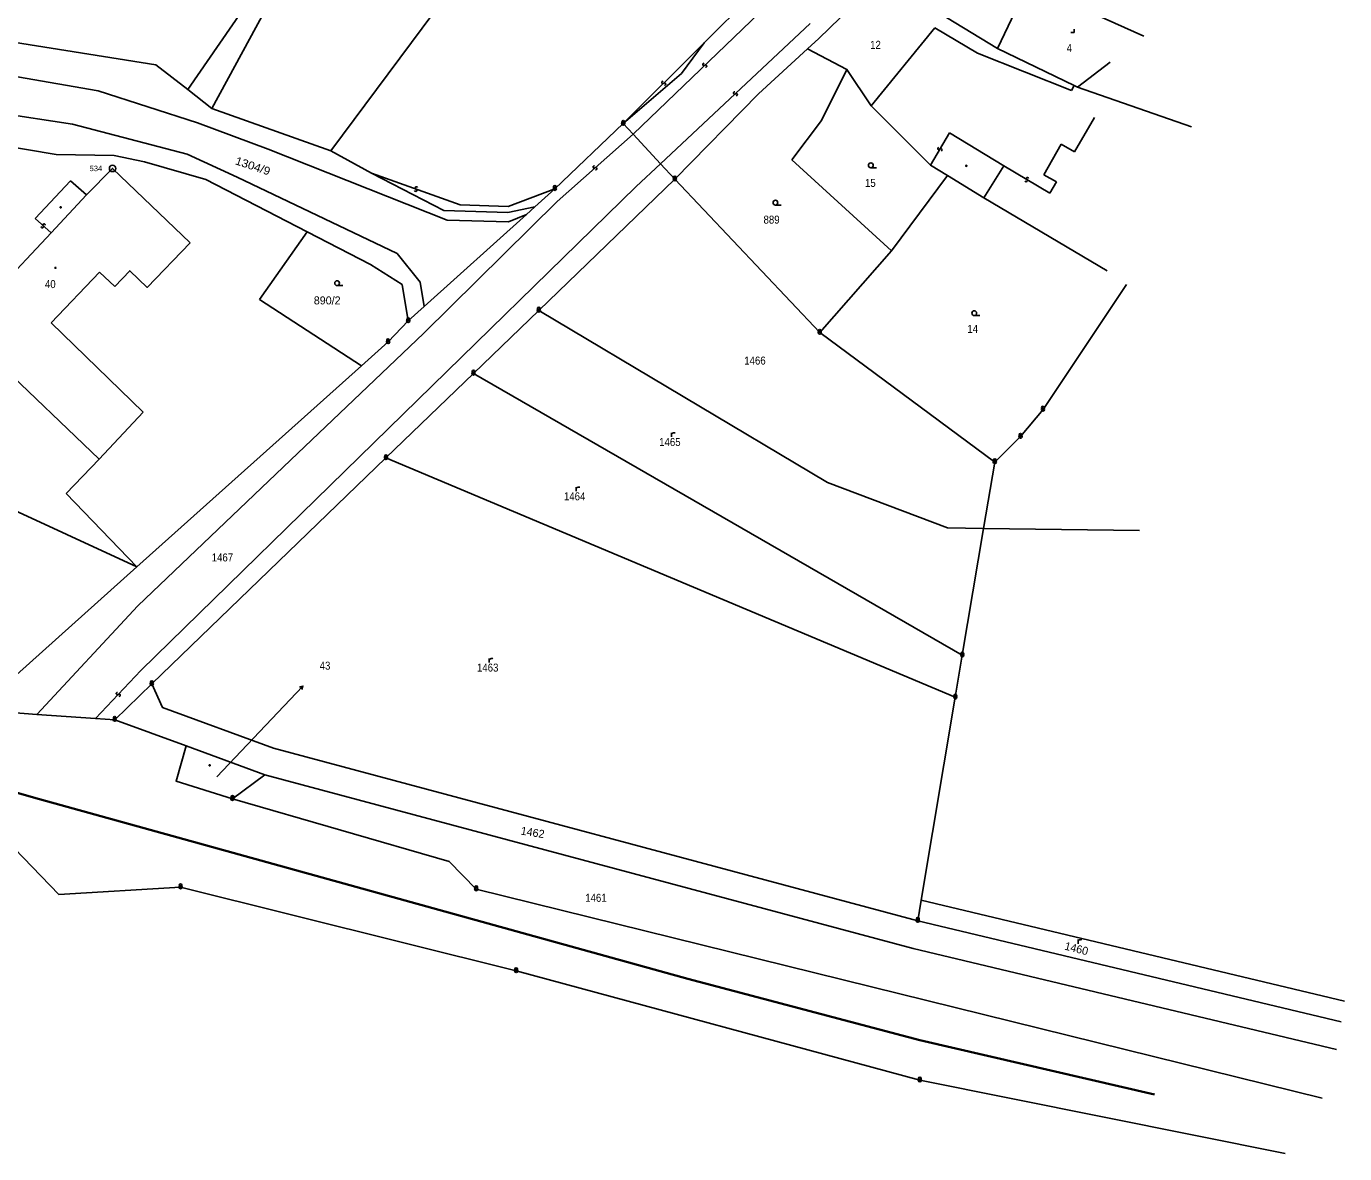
# Model space of a CAD drawing. Extents: x -871901 to -870967, y -1075952 to -1074892.
# Drawn here: x -871194.5 to -871029.7, y -1075430.9 to -1075290 of the extents above; entities that cross this region are included whole.
import ezdxf
from ezdxf.enums import TextEntityAlignment as Align

# ---------------------------------------------------------------- set-up
doc = ezdxf.new("R2010")
doc.units = 0
doc.header["$LTSCALE"] = 0.4
for name, color, linetype, lineweight in [('1', 7, 'Continuous', 25), ('10', 7, 'Continuous', 35), ('16', 7, 'Continuous', 25), ('24', 7, 'Continuous', 25), ('25', 7, 'Continuous', 25), ('4', 7, 'Continuous', 25)]:
    doc.layers.add(name, color=color, linetype=linetype, lineweight=lineweight)
for name, color, linetype in [('17', 7, 'Continuous'), ('18', 7, 'Continuous'), ('19', 7, 'Continuous')]:
    doc.layers.add(name, color=color, linetype=linetype)

msp = doc.modelspace()

# ---------------------------------------------------------------- linework, layer by layer
at = {"layer": '1'}
for p, q in [((-871156.43, -1075305.59), (-871115.7, -1075250.9)), ((-871174.28, -1075297.93), (-871154.05, -1075268.6)), ((-871109.75, -1075292.07), (-871095.22, -1075277.55)), ((-871095.43, -1075291.53), (-871087.07, -1075283.41)), ((-871073.1, -1075292.79), (-871069.29, -1075284.78)), ((-871084.21, -1075286.02), (-871073.1, -1075292.79)), ((-871064.49, -1075286.92), (-871054.81, -1075291.23)), ((-871088.88, -1075299.94), (-871080.94, -1075290.22)), ((-871080.94, -1075290.22), (-871075.62, -1075293.36)), ((-871197.94, -1075291.72), (-871178.28, -1075294.81)), ((-871112.61, -1075295.91), (-871109.75, -1075292.07)), ((-871096.84, -1075292.82), (-871095.43, -1075291.53)), ((-871102.97, -1075298.45), (-871096.84, -1075292.82)), ((-871096.84, -1075292.82), (-871091.92, -1075295.42)), ((-871075.62, -1075293.36), (-871063.87, -1075298.04)), ((-871073.1, -1075292.79), (-871063.52, -1075297.41)), ((-871178.28, -1075294.81), (-871174.28, -1075297.93)), ((-871119.87, -1075302.18), (-871112.61, -1075295.91)), ((-871063.87, -1075298.04), (-871063.52, -1075297.41)), ((-871174.28, -1075297.93), (-871171.28, -1075300.27)), ((-871113.42, -1075309.13), (-871102.97, -1075298.45)), ((-871063.11, -1075297.61), (-871048.84, -1075302.56)), ((-871171.28, -1075300.27), (-871156.43, -1075305.59)), ((-871088.88, -1075299.94), (-871081.48, -1075307.38)), ((-871128.42, -1075310.32), (-871119.87, -1075302.18)), ((-871119.87, -1075302.18), (-871118.65, -1075303.5)), ((-871098.8, -1075306.71), (-871095.1, -1075301.79)), ((-871118.65, -1075303.5), (-871115.21, -1075307.2)), ((-871198.89, -1075304.69), (-871190.75, -1075306.03)), ((-871156.43, -1075305.59), (-871151.31, -1075308.38)), ((-871190.75, -1075306.03), (-871183.47, -1075306.17)), ((-871183.47, -1075306.17), (-871179.69, -1075306.97)), ((-871179.69, -1075306.97), (-871172.04, -1075309.18)), ((-871115.21, -1075307.2), (-871113.42, -1075309.13)), ((-871098.8, -1075306.71), (-871086.34, -1075318.08)), ((-871151.31, -1075308.38), (-871142.29, -1075313.05)), ((-871086.34, -1075318.08), (-871079.33, -1075308.68)), ((-871172.04, -1075309.18), (-871159.38, -1075315.72)), ((-871113.42, -1075309.13), (-871095.32, -1075328.3)), ((-871074.79, -1075311.44), (-871059.4, -1075320.6)), ((-871142.29, -1075313.05), (-871134.29, -1075313.31)), ((-871134.29, -1075313.31), (-871130.92, -1075312.57)), ((-871165.34, -1075324.15), (-871159.38, -1075315.72)), ((-871159.38, -1075315.72), (-871151.47, -1075319.8)), ((-871095.32, -1075328.3), (-871086.34, -1075318.08)), ((-871151.47, -1075319.8), (-871147.48, -1075322.31)), ((-871147.48, -1075322.31), (-871146.74, -1075326.85)), ((-871067.41, -1075337.92), (-871056.96, -1075322.27)), ((-871165.34, -1075324.15), (-871152.59, -1075332.45)), ((-871149.26, -1075329.47), (-871146.74, -1075326.85)), ((-871130.43, -1075325.54), (-871094.35, -1075347.04)), ((-871202.55, -1075327.7), (-871185.37, -1075344.12)), ((-871095.32, -1075328.3), (-871073.44, -1075344.48)), ((-871152.59, -1075332.45), (-871149.26, -1075329.47)), ((-871180.67, -1075357.59), (-871152.59, -1075332.45)), ((-871138.58, -1075333.41), (-871077.5, -1075368.64)), ((-871070.22, -1075341.31), (-871067.41, -1075337.92)), ((-871218.91, -1075339.87), (-871180.67, -1075357.59)), ((-871073.44, -1075344.48), (-871070.22, -1075341.31)), ((-871189.49, -1075348.43), (-871185.37, -1075344.12)), ((-871078.37, -1075373.89), (-871149.52, -1075343.97)), ((-871189.49, -1075348.43), (-871180.67, -1075357.59))]:
    msp.add_line(p, q, dxfattribs=at)
for points in [[(-871095.1, -1075301.79), (-871091.92, -1075295.42), (-871088.88, -1075299.94)], [(-871063.52, -1075297.41), (-871063.11, -1075297.61), (-871059.04, -1075294.48)], [(-871081.48, -1075307.38), (-871079.33, -1075308.68), (-871074.79, -1075311.44)], [(-871183.42, -1075376.69), (-871178.79, -1075372.22), (-871149.52, -1075343.97), (-871138.58, -1075333.41), (-871130.43, -1075325.54), (-871113.42, -1075309.13)], [(-871131.97, -1075313.52), (-871130.92, -1075312.57), (-871128.42, -1075310.32)], [(-871146.74, -1075326.85), (-871144.74, -1075325.04), (-871131.97, -1075313.52)], [(-871073.44, -1075344.48), (-871074.84, -1075352.78), (-871055.34, -1075353.05)], [(-871094.35, -1075347.04), (-871079.33, -1075352.72), (-871074.84, -1075352.78)], [(-871029.72, -1075411.9), (-871082.62, -1075399.25), (-871078.37, -1075373.89), (-871077.5, -1075368.64), (-871074.84, -1075352.78)], [(-871201.2, -1075375.48), (-871200.62, -1075375.46), (-871180.67, -1075357.59)], [(-871178.79, -1075372.22), (-871177.43, -1075375.17), (-871163.59, -1075380.25), (-871083.05, -1075401.82)], [(-871200.62, -1075375.46), (-871193.17, -1075376.03), (-871185.81, -1075376.53), (-871183.42, -1075376.69)], [(-871183.42, -1075376.69), (-871174.48, -1075379.98), (-871175.76, -1075384.38), (-871168.71, -1075386.58), (-871141.62, -1075394.43), (-871138.24, -1075397.87), (-871032.51, -1075424.01)], [(-871174.48, -1075379.98), (-871164.66, -1075383.59), (-871168.71, -1075386.58)], [(-871164.66, -1075383.59), (-871083.63, -1075405.29), (-871030.73, -1075417.93)], [(-871212.24, -1075392.84), (-871205.94, -1075388.38), (-871204.62, -1075388.86), (-871199.28, -1075390.81), (-871197.08, -1075391.62), (-871190.41, -1075398.53), (-871175.19, -1075397.63)], [(-871037.17, -1075430.94), (-871082.81, -1075421.77), (-871133.25, -1075408.1), (-871175.19, -1075397.63)], [(-871082.62, -1075399.25), (-871083.05, -1075401.82), (-871030.15, -1075414.48)]]:
    msp.add_lwpolyline(points, dxfattribs=at)
at = {"layer": '10'}
msp.add_lwpolyline([(-871303.26, -1075354.3), (-871283.38, -1075360.82), (-871232.19, -1075375.42), (-871192.83, -1075386.61), (-871111.78, -1075409.09), (-871082.8, -1075416.75), (-871053.48, -1075423.53)], dxfattribs=at)
at = {"layer": '16'}
for p, q in [((-871160.73, -1075373.36), (-871159.903, -1075372.489)), ((-871170.66, -1075383.82), (-871160.73, -1075373.36))]:
    msp.add_line(p, q, dxfattribs=at)
msp.add_lwpolyline([(-871160.324, -1075372.642), (-871159.903, -1075372.489), (-871160.034, -1075372.917)], dxfattribs=at)
at = {"layer": '24'}
for centre, radius in [((-871119.8695, -1075302.1795), 0.2005), ((-871119.8695, -1075302.1795), 0.00851), ((-871183.6895, -1075307.7795), 0.4005), ((-871183.6895, -1075307.7795), 0.0125), ((-871113.4195, -1075309.1295), 0.2005), ((-871128.4195, -1075310.3195), 0.2005), ((-871128.4195, -1075310.3195), 0.00851), ((-871113.4195, -1075309.1295), 0.00851), ((-871130.4295, -1075325.5395), 0.2005), ((-871146.7395, -1075326.8495), 0.2005), ((-871146.7395, -1075326.8495), 0.00851), ((-871130.4295, -1075325.5395), 0.00851), ((-871095.3195, -1075328.2995), 0.2005), ((-871095.3195, -1075328.2995), 0.00851), ((-871149.2595, -1075329.4695), 0.2005), ((-871149.2595, -1075329.4695), 0.00851), ((-871138.5795, -1075333.4095), 0.2005), ((-871138.5795, -1075333.4095), 0.00851), ((-871067.4095, -1075337.9195), 0.2005), ((-871067.4095, -1075337.9195), 0.00851), ((-871070.2195, -1075341.3095), 0.2005), ((-871070.2195, -1075341.3095), 0.00851), ((-871149.5195, -1075343.9695), 0.2005), ((-871149.5195, -1075343.9695), 0.00851), ((-871073.4395, -1075344.4795), 0.2005), ((-871073.4395, -1075344.4795), 0.00851), ((-871077.4995, -1075368.6395), 0.2005), ((-871077.4995, -1075368.6395), 0.00851), ((-871178.7895, -1075372.2195), 0.2005), ((-871178.7895, -1075372.2195), 0.00851), ((-871078.3695, -1075373.8895), 0.2005), ((-871078.3695, -1075373.8895), 0.00851), ((-871183.4195, -1075376.6895), 0.2005), ((-871183.4195, -1075376.6895), 0.00851), ((-871168.7095, -1075386.5795), 0.2005), ((-871168.7095, -1075386.5795), 0.00851), ((-871175.1895, -1075397.6295), 0.2005), ((-871175.1895, -1075397.6295), 0.00851), ((-871138.2395, -1075397.8695), 0.2005), ((-871138.2395, -1075397.8695), 0.00851), ((-871083.0495, -1075401.8195), 0.2005), ((-871083.0495, -1075401.8195), 0.00851), ((-871133.2495, -1075408.0995), 0.2005), ((-871133.2495, -1075408.0995), 0.00851), ((-871082.8095, -1075421.7695), 0.2005), ((-871082.8095, -1075421.7695), 0.00851)]:
    msp.add_circle(centre, radius, dxfattribs=at)
for centre in [(-871119.8698, -1075301.9536), (-871113.4198, -1075308.9036), (-871128.4198, -1075310.0936), (-871130.4298, -1075325.3136), (-871146.7398, -1075326.6236), (-871095.3198, -1075328.0736), (-871149.2598, -1075329.2436), (-871138.5798, -1075333.1836), (-871067.4098, -1075337.6936), (-871070.2198, -1075341.0836), (-871149.5198, -1075343.7436), (-871073.4398, -1075344.2536), (-871077.4998, -1075368.4136), (-871178.7898, -1075371.9936), (-871078.3698, -1075373.6636), (-871183.4198, -1075376.4636), (-871168.7098, -1075386.3536), (-871175.1898, -1075397.4036), (-871138.2398, -1075397.6436), (-871083.0498, -1075401.5936), (-871133.2498, -1075407.8736), (-871082.8098, -1075421.5436)]:
    msp.add_arc(centre, 0.1746, 328.19485, 209.95045, dxfattribs=at)
at = {"layer": '25'}
for p, q in [((-871088.93, -1075307.69), (-871088.229, -1075307.69)), ((-871100.85, -1075312.36), (-871100.149, -1075312.36)), ((-871155.63, -1075322.42), (-871154.929, -1075322.42)), ((-871076.01, -1075326.18), (-871075.309, -1075326.18)), ((-871113.86, -1075341.35), (-871113.86, -1075340.829)), ((-871125.76, -1075348.14), (-871125.76, -1075347.619)), ((-871136.63, -1075369.55), (-871136.63, -1075369.029)), ((-871063.04, -1075404.7), (-871063.04, -1075404.179))]:
    msp.add_line(p, q, dxfattribs=at)
for points in [[(-871063.92, -1075290.78), (-871063.52, -1075290.78), (-871063.52, -1075290.379)], [(-871113.86, -1075340.993), (-871113.788, -1075340.922), (-871113.709, -1075340.877), (-871113.597, -1075340.847), (-871113.492, -1075340.828), (-871113.379, -1075340.821)], [(-871125.76, -1075347.783), (-871125.688, -1075347.712), (-871125.609, -1075347.667), (-871125.497, -1075347.637), (-871125.392, -1075347.618), (-871125.279, -1075347.611)], [(-871136.63, -1075369.193), (-871136.558, -1075369.122), (-871136.479, -1075369.077), (-871136.367, -1075369.047), (-871136.262, -1075369.028), (-871136.149, -1075369.021)], [(-871063.04, -1075404.343), (-871062.968, -1075404.272), (-871062.889, -1075404.227), (-871062.777, -1075404.197), (-871062.672, -1075404.178), (-871062.559, -1075404.171)]]:
    msp.add_lwpolyline(points, dxfattribs=at)
for centre, radius in [((-871088.9295, -1075307.3895), 0.3005), ((-871076.9895, -1075307.4595), 0.0705), ((-871100.8495, -1075312.0595), 0.3005), ((-871190.1695, -1075312.6395), 0.0705), ((-871190.8195, -1075320.1995), 0.0705), ((-871155.6295, -1075322.1195), 0.3005), ((-871076.0095, -1075325.8795), 0.3005), ((-871171.5595, -1075382.3995), 0.0705)]:
    msp.add_circle(centre, radius, dxfattribs=at)
for centre, radius, start, end in [((-871109.7806, -1075294.7725), 0.1472, 81.83777, 313.35019), ((-871109.5787, -1075294.9872), 0.1475, 261.43294, 134.0168), ((-871114.9125, -1075297.0247), 0.147, 83.24198, 314.4516), ((-871114.7068, -1075297.235), 0.1472, 262.58746, 135.11537), ((-871105.949, -1075298.3311), 0.1471, 81.37645, 312.25), ((-871105.7502, -1075298.5485), 0.1474, 260.60384, 132.73808), ((-871080.4258, -1075305.2939), 0.147, 97.62277, 328.9053), ((-871080.1733, -1075305.4455), 0.1475, 276.59894, 149.44003), ((-871123.4956, -1075307.5978), 0.1474, 79.07114, 309.74666), ((-871123.303, -1075307.8206), 0.1471, 258.3086, 131.15041), ((-871069.3633, -1075309.0444), 0.1472, 6.13111, 238.57233), ((-871145.8214, -1075310.4981), 0.1473, 197.33245, 69.72086), ((-871145.7191, -1075310.222), 0.1471, 17.95263, 249.71943), ((-871069.5167, -1075309.2956), 0.1472, 186.25551, 58.36101), ((-871192.4495, -1075315.0681), 0.147, 175.30271, 47.46097), ((-871192.2501, -1075314.8514), 0.1476, 355.20665, 227.46757), ((-871183.0859, -1075373.4275), 0.1474, 84.5839, 316.10422), ((-871182.8737, -1075373.6323), 0.1475, 264.17576, 136.75989)]:
    msp.add_arc(centre, radius, start, end, dxfattribs=at)
at = {"layer": '4'}
for p, q in [((-871171.28, -1075300.27), (-871154.05, -1075268.6)), ((-871118.65, -1075303.5), (-871100.71, -1075286.26)), ((-871115.21, -1075307.2), (-871096.49, -1075289.67)), ((-871119.87, -1075302.18), (-871109.75, -1075292.07)), ((-871195.57, -1075296.31), (-871185.5, -1075298.06)), ((-871185.5, -1075298.06), (-871173.09, -1075302.09)), ((-871198.04, -1075300.83), (-871188.7, -1075302.25)), ((-871188.7, -1075302.25), (-871174.37, -1075306)), ((-871173.09, -1075302.09), (-871164.26, -1075305.38)), ((-871063.47, -1075305.69), (-871060.98, -1075301.4)), ((-871081.48, -1075307.38), (-871079.11, -1075303.35)), ((-871079.11, -1075303.35), (-871072.32, -1075307.44)), ((-871164.26, -1075305.38), (-871141.89, -1075314.23)), ((-871067.33, -1075308.58), (-871065.15, -1075304.76)), ((-871065.15, -1075304.76), (-871063.47, -1075305.69)), ((-871174.37, -1075306), (-871168.13, -1075308.89)), ((-871186.94, -1075311.08), (-871183.69, -1075307.78)), ((-871183.69, -1075307.78), (-871174, -1075317.1)), ((-871168.13, -1075308.89), (-871148.13, -1075318.4)), ((-871151.31, -1075308.38), (-871140.23, -1075312.34)), ((-871074.79, -1075311.44), (-871072.32, -1075307.44)), ((-871072.32, -1075307.44), (-871066.57, -1075310.89)), ((-871067.33, -1075308.58), (-871065.73, -1075309.46)), ((-871193.35, -1075314.06), (-871188.96, -1075309.34)), ((-871188.96, -1075309.34), (-871186.94, -1075311.08)), ((-871134.25, -1075312.54), (-871128.42, -1075310.32)), ((-871066.57, -1075310.89), (-871065.73, -1075309.46)), ((-871191.36, -1075315.85), (-871186.94, -1075311.08)), ((-871140.23, -1075312.34), (-871134.25, -1075312.54)), ((-871134.21, -1075314.46), (-871131.97, -1075313.52)), ((-871193.35, -1075314.06), (-871191.36, -1075315.85)), ((-871141.89, -1075314.23), (-871134.21, -1075314.46)), ((-871202.55, -1075327.7), (-871191.36, -1075315.85)), ((-871191.36, -1075327.09), (-871185.32, -1075320.73)), ((-871185.32, -1075320.73), (-871183.41, -1075322.55)), ((-871191.36, -1075327.09), (-871179.85, -1075338.26)), ((-871185.37, -1075344.12), (-871179.85, -1075338.26))]:
    msp.add_line(p, q, dxfattribs=at)
for points in [[(-871118.65, -1075303.5), (-871128.14, -1075311.92), (-871144.78, -1075328.38), (-871161.44, -1075344.27), (-871180.53, -1075362.44), (-871193.17, -1075376.03)], [(-871185.81, -1075376.53), (-871180.16, -1075370.54), (-871118.25, -1075310.04), (-871115.21, -1075307.2)], [(-871183.41, -1075322.55), (-871181.54, -1075320.58), (-871179.36, -1075322.65), (-871174, -1075317.1)], [(-871148.13, -1075318.4), (-871145.25, -1075321.99), (-871144.74, -1075325.04)]]:
    msp.add_lwpolyline(points, dxfattribs=at)

# ---------------------------------------------------------------- texts
at = {"layer": '16', "width": 0.9}
msp.add_text('43', height=1, dxfattribs=at).set_placement((-871157.1395, -1075370.44), align=Align.CENTER)
at = {"layer": '17', "width": 0.9}
msp.add_text('534', height=0.68, dxfattribs=at).set_placement((-871184.99, -1075308.12), align=Align.RIGHT)
at = {"layer": '18', "width": 0.9}
for s, p in [('12', (-871089.02, -1075292.83)), ('15', (-871089.66, -1075310.09)), ('889', (-871102.34, -1075314.68)), ('14', (-871076.87, -1075328.34)), ('1466', (-871104.75, -1075332.3)), ('1465', (-871115.38, -1075342.48)), ('1464', (-871127.28, -1075349.27)), ('1467', (-871171.3, -1075356.91)), ('1463', (-871138.15, -1075370.68)), ('1461', (-871124.62, -1075399.46))]:
    msp.add_text(s, height=1, dxfattribs=at).set_placement(p)
at = {"layer": '18', "width": 1.1}
msp.add_text('1304/9', height=1, rotation=341.403, dxfattribs=at).set_placement((-871168.447, -1075307.235))
at = {"layer": '18'}
msp.add_text('890/2', height=1, dxfattribs=at).set_placement((-871158.54, -1075324.78))
for s, rotation, p in [('1462', 351.003, (-871132.732, -1075391.044)), ('1460', 345.603, (-871064.797, -1075405.417))]:
    msp.add_text(s, height=1, rotation=rotation, dxfattribs=at).set_placement(p)
at = {"layer": '19', "width": 0.9}
for s, p in [('4', (-871064.46, -1075293.23)), ('40', (-871192.14, -1075322.74))]:
    msp.add_text(s, height=1, dxfattribs=at).set_placement(p)
msp.add_text('43', height=0.1, dxfattribs=at).set_placement((-871170.4895, -1075383.74), align=Align.CENTER)

doc.saveas('drawing.dxf')
